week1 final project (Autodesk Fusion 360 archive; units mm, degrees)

design "soko"
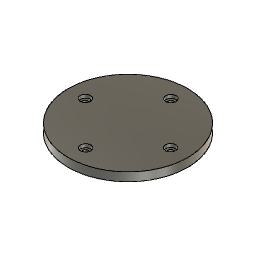
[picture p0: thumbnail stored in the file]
sketch "スケッチ1" plane through (0, 0, 0) normal (0, 0, 1) x axis (1, 0, 0)
  circle C1 centre (-0.1594, 0) radius 35
  dimension "d1" diameter C1 = 70
extrude "押し出し1" new body sketch "スケッチ1" along normal blind 5
sketch "スケッチ2" plane through (0, 0, 5) normal (0, 0, 1) x axis (-1, 0, 0)
  line L1 (0, 53.2942) -> (0, -50.1057)
  line L2 (-53.5157, 0) -> (46.9792, 0)
  circle C1 centre (0.1594, 0) radius 35
  circle C2 centre (0.1594, 0) radius 25
  circle C3 centre (0, -24.9995) radius 1.55
  circle C4 centre (-24.8406, 0) radius 1.55
  circle C5 centre (25.1594, 0) radius 1.55
  circle C6 centre (0, 24.9995) radius 1.55
  point P1 (0, 0)
  point P10 (25.1594, 0)
  point P8 (0, -24.9995)
  point P9 (-24.8406, 0)
  point P11 (0, 24.9995)
  vertical L1
  horizontal L2
  coincident P1 L1
  coincident P1 L2
  concentric C1 C2
  coincident C2 P10
  coincident L2 P10
  coincident L1 P8
  coincident C2 P8
  equal C3 C5
  equal C4 C5
  coincident L2 P9
  coincident C2 P9
  coincident L1 P11
  coincident C2 P11
  equal C5 C6
  dimension "d4" diameter C2 = 50
  dimension "d5" diameter C5 = 3.1
extrude "押し出し2" cut sketch "スケッチ2" profile of L1 L2 C2 C3 C4 C5 C6 against normal blind 5
sketch "スケッチ3" plane through (0, 0, 5) normal (0, 0, 1) x axis (-1, 0, 0)
  circle C1 centre (-24.8406, 0) radius 1.55
  circle C2 centre (0, 24.9995) radius 1.55
  circle C3 centre (0, -24.9995) radius 1.55
  circle C4 centre (25.1594, 0) radius 1.55
  circle C5 centre (0.1594, 0) radius 35
  circle C6 centre (25.1594, 0) radius 3
  circle C7 centre (0, -24.9995) radius 3
  circle C8 centre (-24.8406, 0) radius 3
  circle C9 centre (0, 24.9995) radius 3
  concentric C4 C6
  concentric C3 C7
  concentric C1 C8
  concentric C2 C9
  equal C6 C7
  equal C7 C8
  equal C8 C9
  dimension "d8" diameter C6 = 6
extrude "押し出し3" cut sketch "スケッチ3" profile of C1 C2 C3 C4 C6 C7 C8 C9 against normal blind 2

design "botom"
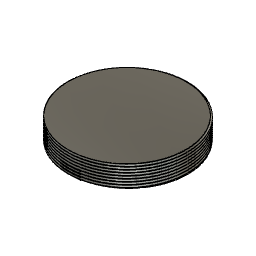
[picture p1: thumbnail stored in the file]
sketch "スケッチ1" plane through (0, 0, 0) normal (0, 0, 1) x axis (1, 0, 0)
  circle C1 centre (0, 0.8768) radius 32
  dimension "d1" diameter C1 = 64
extrude "押し出し1" new body sketch "スケッチ1" along normal blind 12
shell "シェル" innerThickness 2
thread "ねじ" ThreadOffset 0 ThreadLength 10
sketch "スケッチ3" plane through (0, 0, 0) normal (0, 0, -1) x axis (1, 0, 0)
  curve K1 (-13.8903, -30.0459) -> (-17.8968, 25.0373)
  curve K2 (17.8968, 25.0373) -> (13.8903, -30.0459)
  arc A1 centre (0, -0.8768) radius 32.3075 clockwise from (13.8903, -30.0459) to (-13.8903, -30.0459)
  arc A2 centre (0, -0.8768) radius 31.4935 clockwise from (-17.8968, 25.0373) to (17.8968, 25.0373)
  circle C1 centre (0, -0.8768) radius 30
sketch "スケッチ2" plane through (0, 0, 0) normal (0, 0, -1) x axis (1, 0, 0)
  curve K1 (-13.8903, -30.0459) -> (-17.8968, 25.0373)
  curve K2 (17.8968, 25.0373) -> (13.8903, -30.0459)
  line L1 (0, 40.4092) -> (0, -38)
  line L2 (-44, 0) -> (43.594, 0)
  line L3 (4.3082, -20.3896) -> (5.5329, -30.3622)
  line L4 (-4.3082, -20.3896) -> (4.3082, -20.3896)
  line L5 (-5.5329, -30.3622) -> (-4.3082, -20.3896)
  arc A1 centre (0, -0.8768) radius 32.3075 clockwise from (13.8903, -30.0459) to (-13.8903, -30.0459)
  arc A2 centre (0, -0.8768) radius 31.4935 clockwise from (-17.8968, 25.0373) to (17.8968, 25.0373)
  circle C1 centre (0, -0.8768) radius 30
  circle C2 centre (0, 0) radius 30
  circle C3 centre (0, 0) radius 25
  circle C4 centre (0, -25) radius 2.25
  circle C5 centre (0, -0.8768) radius 30
  point P1 (0, 0)
  point P7 (0, 0)
  point P13 (0, -25)
  point P8 (0, 0)
  point P18 (-5.5329, -30.3622)
  point P15 (5.5329, -30.3622)
  coincident P1 P7
  vertical L1
  horizontal L2
  concentric C2 C3
  coincident L1 P13
  coincident C3 P13
  coincident P8 L2
  coincident P7 L1
  symmetric L1 L3 L5
  coincident C5 P18
  coincident C5 P15
  horizontal L4
  dimension "d7" diameter C2 = 60
  dimension "d8" diameter C3 = 50
extrude "押し出し4" new body sketch "スケッチ2" profile of C1 C2 C3 L1 C4 C5 L3 L4 L5 against normal blind 5
circular_pattern "C パターン" TotalAngle 360
combine "結合"
fillet "フィレット" radius 2

design "final"
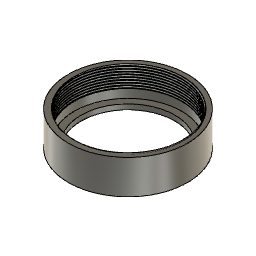
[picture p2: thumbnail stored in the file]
sketch "スケッチ1" plane through (0, 0, 0) normal (0, 0, 1) x axis (1, 0, 0)
  circle C1 centre (0, 0) radius 35
  point P1 (0, 0)
  point P2 (0, 0)
  coincident P1 P2
  dimension "d1" diameter C1 = 70
extrude "押し出し1" new body sketch "スケッチ1" along normal blind 20
shell "シェル" sketch "スケッチ1" innerThickness 3
thread "ねじ" sketch "スケッチ1" ThreadOffset 0 ThreadLength 10
sketch "スケッチ2" plane through (0, 0, 0) normal (0, 0, 1) x axis (1, 0, 0)
  circle C1 centre (0, 0) radius 27.5
  point P1 (0, 0)
  point P2 (0, 0)
  coincident P1 P2
  dimension "d7" diameter C1 = 55
extrude "押し出し2" cut sketch "スケッチ2" + "スケッチ1" profile of S1:C1 blind 3
sketch "スケッチ3" plane through (0, 0, 0) normal (0, 0, 1) x axis (1, 0, 0)
  circle C1 centre (0, 0) radius 33.6575
  circle C2 centre (0, 0) radius 31.5
  point P1 (0, 0)
  point P2 (0, 0)
  coincident P1 P2
  concentric C1 C2
  dimension "d10" diameter C1 = 67.315
  dimension "d11" diameter C2 = 63
extrude "押し出し3" new body sketch "スケッチ3" + "スケッチ1" profile of S1:C1 S1:C2 blind 8
combine "結合" sketch "スケッチ1"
